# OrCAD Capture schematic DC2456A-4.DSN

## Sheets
1 PAGE3: size A
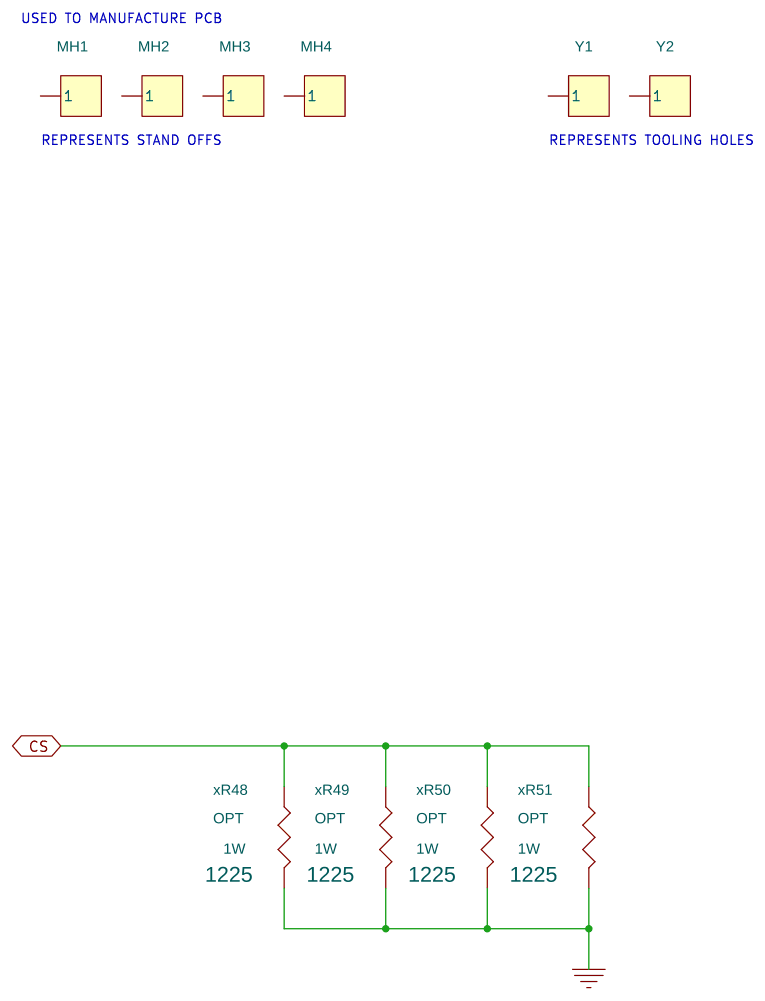
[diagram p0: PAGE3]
2 PAGE2: size B; title: HIGH EFFICIENCY HIGH VOLTAGE; rev: 4; company: TM; note: BUCK-BOOST CONVERTER
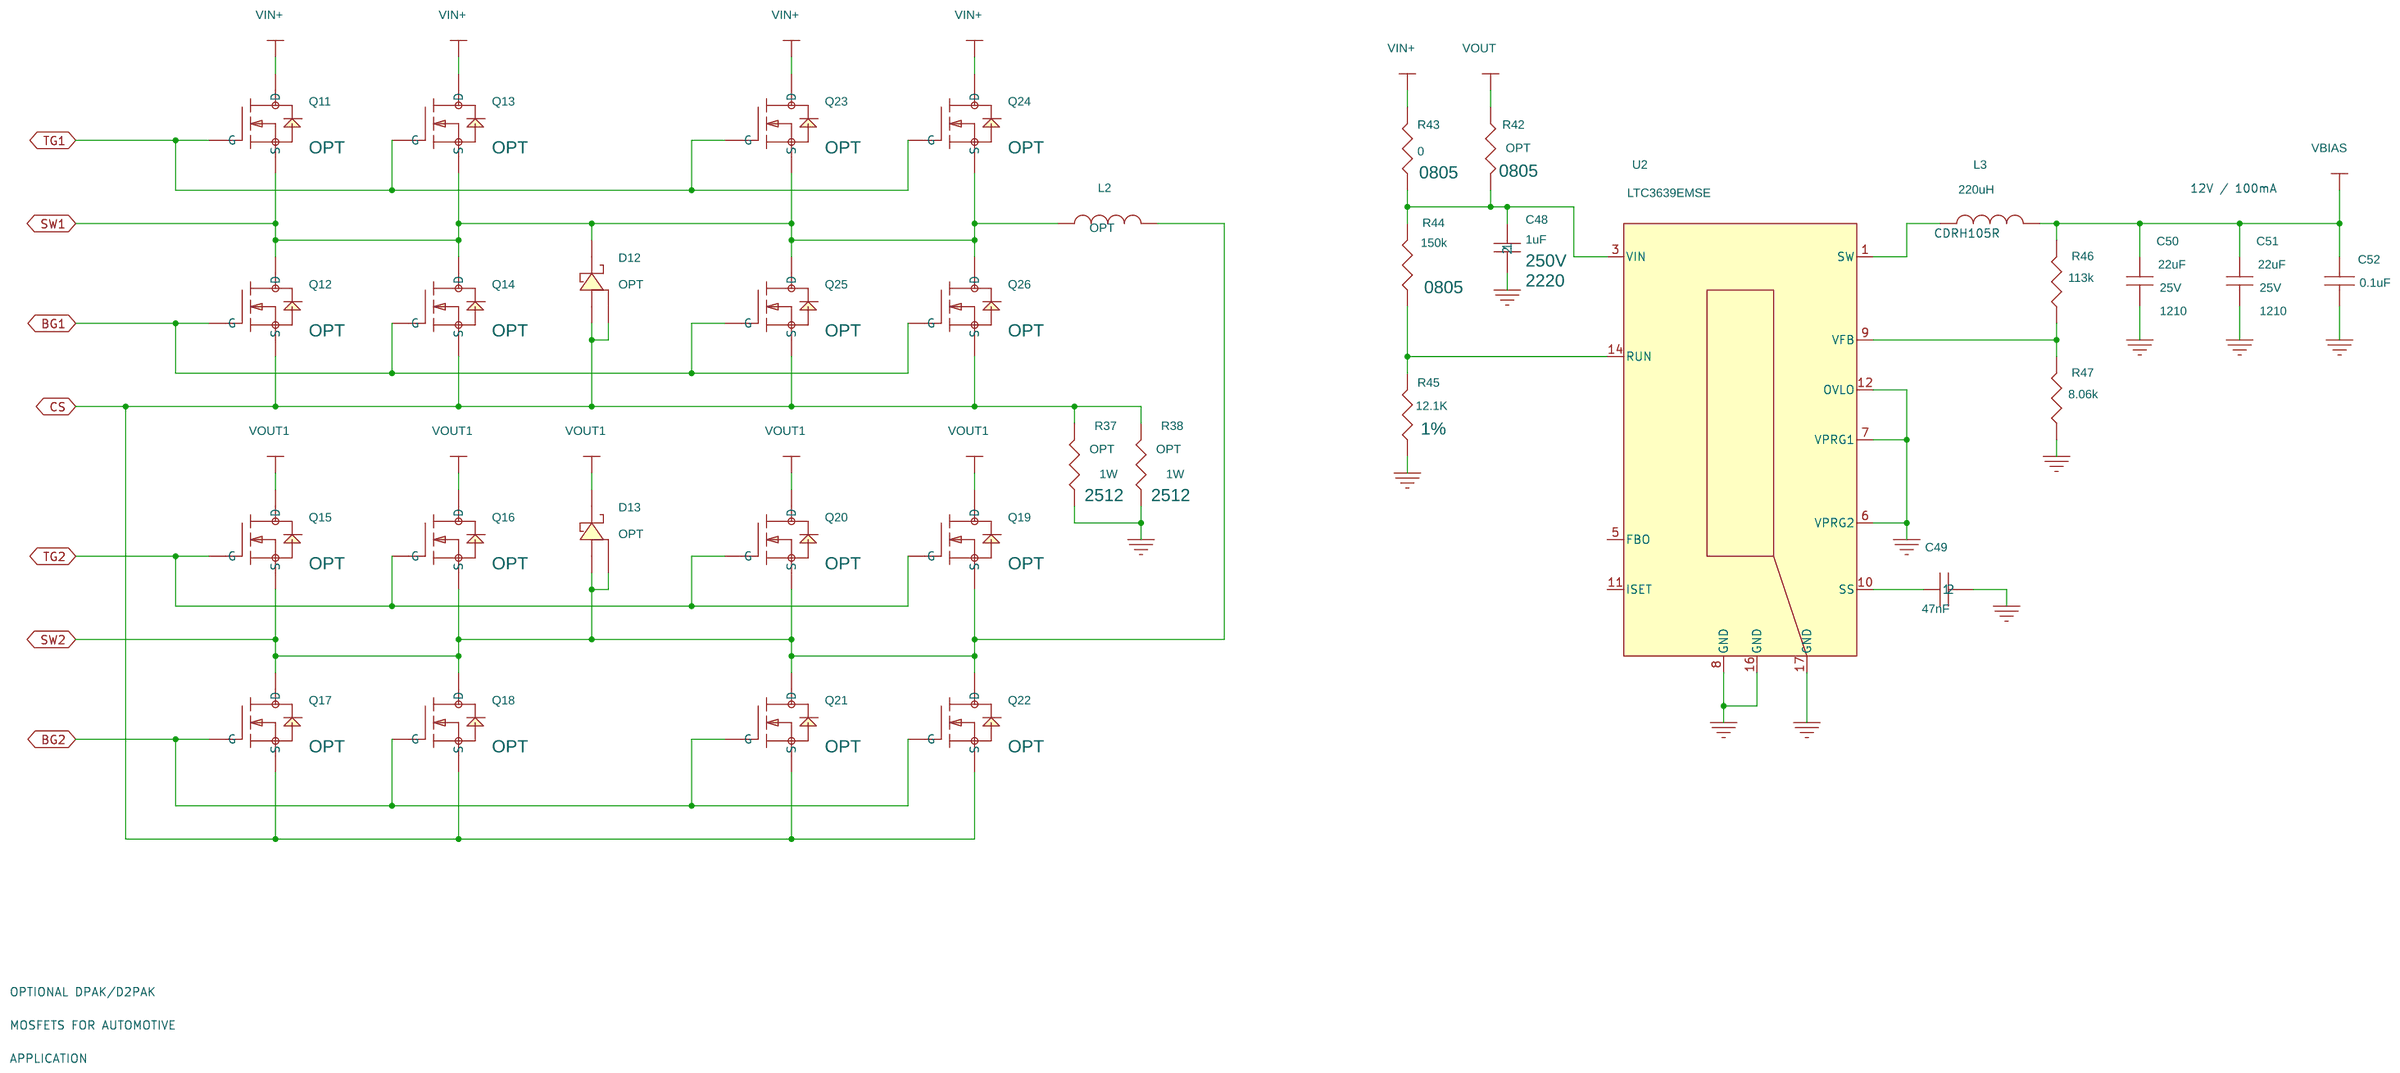
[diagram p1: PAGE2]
3 PAGE1: size Custom; title: HIGH EFFICIENCY HIGH VOLTAGE; rev: 4; company: TM; note: BUCK-BOOST CONVERTER
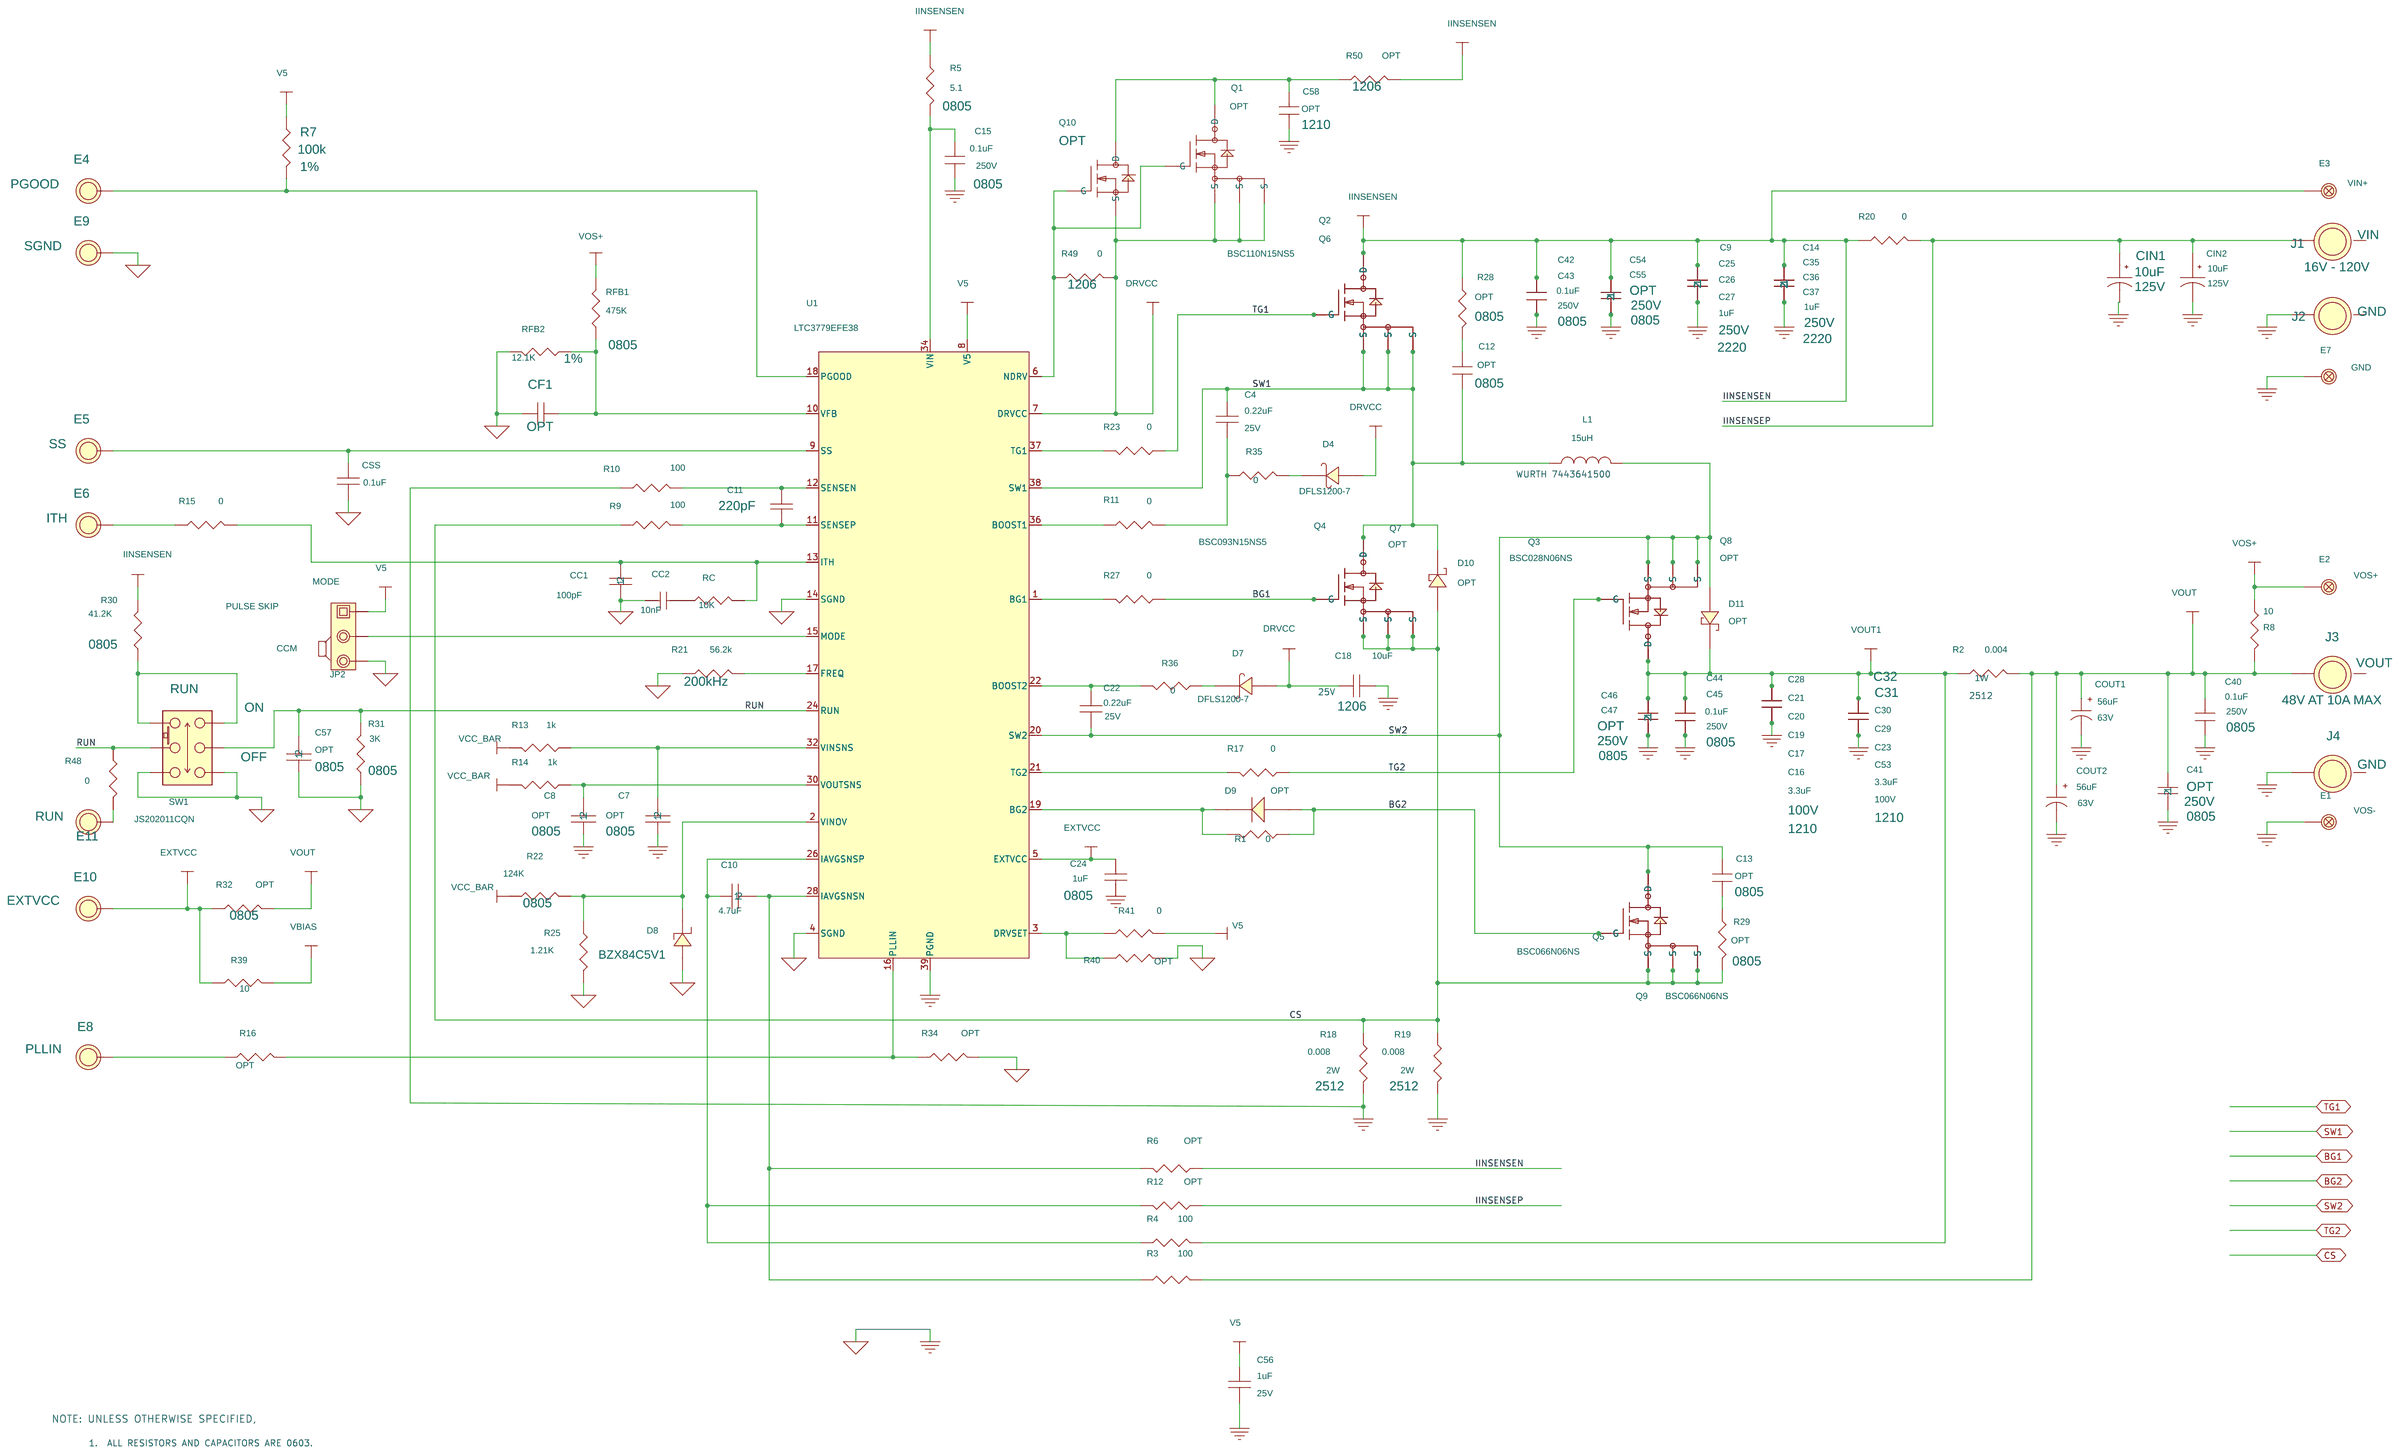
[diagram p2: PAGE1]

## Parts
sheet PAGE1
C4  0.22uF  [0603]
C7  OPT  [0805]
C8  OPT  [0805]
C9  1uF  [2220]
C10  4.7uF  [0603]
C11  220pF  [0603]
C12  OPT  [0805]
C13  OPT  [0805]
C14  1uF  [2220]
C15  0.1uF  [0805]
C16  3.3uF  [1210]
C17  3.3uF  [1210]
C18  10uF  [1206]
C19  3.3uF  [1210]
C20  3.3uF  [1210]
C21  3.3uF  [1210]
C22  0.22uF  [0603]
C23  3.3uF  [1210]
C24  1uF  [0805]
C25  1uF  [2220]
C26  1uF  [2220]
C27  1uF  [2220]
C28  3.3uF  [1210]
C29  3.3uF  [1210]
C30  3.3uF  [1210]
C31  3.3uF  [1210]
C32  3.3uF  [1210]
C35  1uF  [2220]
C36  1uF  [2220]
C37  1uF  [2220]
C40  0.1uF  [0805]
C41  0.1uF  [0805]
C42  0.1uF  [0805]
C43  0.1uF  [0805]
C44  0.1uF  [0805]
C45  0.1uF  [0805]
C46  0.1uF  [0805]
C47  0.1uF  [0805]
C53  3.3uF  [1210]
C54  0.1uF  [0805]
C55  0.1uF  [0805]
C56  1uF  [0603]
C57  OPT  [0805]
C58  OPT  [1210]
CC1  100pF  [0603]
CC2  10nF  [0603]
CF1  OPT  [0603]
CIN1  10uF  [CAP\SUN\10.3X10.3]
CIN2  10uF  [CAP\SUN\10.3X10.3]
COUT1  56uF  [CAP\SANYO\SVP\F8\10.3X10.3]
COUT2  56uF  [CAP\SANYO\SVP\F8\10.3X10.3]
CSS  0.1uF  [0603]
D4  DFLS1200-7  [POWERDI123]
D7  DFLS1200-7  [POWERDI123]
D8  BZX84C5V1  [SOT23]
D9  OPT  [SOT23]
D10  OPT  [SMB]
D11  OPT  [SMA-DIODE]
E1  Testpoint  [TP\MMX\2308-2]
E2  Testpoint  [TP\MMX\2308-2]
E3  Testpoint  [TP\MMX\2308-2]
E4  3A  [TP\MMX\2501-2]
E5  3A  [TP\MMX\2501-2]
E6  3A  [TP\MMX\2501-2]
E7  Testpoint  [TP\MMX\2308-2]
E8  3A  [TP\MMX\2501-2]
E9  3A  [TP\MMX\2501-2]
E10  3A  [TP\MMX\2501-2]
E11  3A  [TP\MMX\2501-2]
J1  VIN  [RP325/205]
J2  GND  [RP325/205]
J3  VOUT  [RP325/205]
J4  GND  [RP325/205]
JP2  3 Pins 2mm Ctrs.  [COMMCON2802S03G2]
L1  15uH  [IND\WRTH\7443641500]
Q1  OPT  [XSTR\INFINEON\PG-TDSON-8]
Q2  BSC093N15NS5  [XSTR\INFINEON\PG-TDSON-8]
Q3  BSC028N06NS  [XSTR\INFINEON\PG-TDSON-8]
Q4  BSC093N15NS5  [XSTR\INFINEON\PG-TDSON-8]
Q5  BSC066N06NS  [XSTR\INFINEON\PG-TDSON-8]
Q6  BSC110N15NS5  [XSTR\INFINEON\PG-TDSON-8]
Q7  OPT  [XSTR\INFINEON\PG-TDSON-8]
Q8  OPT  [XSTR\INFINEON\PG-TDSON-8]
Q9  BSC066N06NS  [XSTR\INFINEON\PG-TDSON-8]
Q10  OPT  [TO252AA]
R1  0  [0603]
R2  0.004  [RL3720T-R018-F]
R3  100  [0603]
R4  100  [0603]
R5  5.1  [0805]
R6  OPT  [0603]
R7  100k  [0603]
R8  10  [0603]
R9  100  [0603]
R10  100  [0603]
R11  0  [0603]
R12  OPT  [0603]
R13  1k  [0603]
R14  1k  [0603]
R15  0  [0603]
R16  OPT  [0603]
R17  0  [0603]
R18  0.008  [2512]
R19  0.008  [2512]
R20  0  [RN5326]
R21  56.2k  [0603]
R22  124K  [0805]
R23  0  [0603]
R25  1.21K  [0603]
R27  0  [0603]
R28  OPT  [0805]
R29  OPT  [0805]
R30  41.2K  [0805]
R31  3K  [0805]
R32  OPT  [0805]
R34  OPT  [0603]
R35  0  [0603]
R36  0  [0603]
R39  10  [0603]
R40  OPT  [0603]
R41  0  [0603]
R48  0  [0603]
R49  0  [1206]
R50  OPT  [1206]
RC  10K  [0603]
RFB1  475K  [0805]
RFB2  12.1K  [0603]
SW1  JS202011CQN  [JS202011]
U1  LTC3779EFE38  [LT_FE38_31_4.4]
XJP2  2mm Ctrs.
sheet PAGE2
C48  1uF  [2220]
C49  47nF  [0603]
C50  22uF  [1210]
C51  22uF  [1210]
C52  0.1uF  [0603]
D12  OPT  [POWERDI_5]
D13  OPT  [POWERDI_5]
L2  OPT  [IND\WRTH\7443641500]
L3  220uH  [IND\SUMIDA\CDRH105R\12X12]
Q11  SQD25N15-52-GE3  [TO252AA]
Q12  SQD25N15-52-GE3  [TO252AA]
Q13  SQM85N15-19-GE3  [TO263]
Q14  SQM85N15-19-GE3  [TO263]
Q15  SQD25N15-52-GE3  [TO252AA]
Q16  SQM85N15-19-GE3  [TO263]
Q17  SQD25N15-52-GE3  [TO252AA]
Q18  SQM85N15-19-GE3  [TO263]
Q19  SQM85N15-19-GE3  [TO263]
Q20  SQD25N15-52-GE3  [TO252AA]
Q21  SQD25N15-52-GE3  [TO252AA]
Q22  SQM85N15-19-GE3  [TO263]
Q23  SQD25N15-52-GE3  [TO252AA]
Q24  SQM85N15-19-GE3  [TO263]
Q25  SQD25N15-52-GE3  [TO252AA]
Q26  SQM85N15-19-GE3  [TO263]
R37  OPT  [2512]
R38  OPT  [2512]
R42  OPT  [0805]
R43  0  [0805]
R44  150k  [0805]
R45  12.1K  [0603]
R46  113k  [0603]
R47  8.06k  [0603]
U2  LTC3639EMSE  [LT_MSE16_12]
sheet PAGE3
MH1  CON1  [KEYSTONE_8831]
MH2  CON1  [KEYSTONE_8831]
MH3  CON1  [KEYSTONE_8831]
MH4  CON1  [KEYSTONE_8831]
xR48  OPT  [1225]
xR49  OPT  [1225]
xR50  OPT  [1225]
xR51  OPT  [1225]
Y1  CON1  [TOOL\ALGNHL\70]
Y2  CON1  [TOOL\ALGNHL\70]

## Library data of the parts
C4 C22 = EMK107BJ224MA: CAP, 0603 0.22uF 20% 16V X7R; 1st Part Field: 25V; 3rd Part Field: X7R; 4th Part Field: KEMET; 5th Part Field: C0603C224K4RAC; Part Number: AVX 0603YC224MAT2A; VOLTAGE: 16V
C7 = C_1: CAP, 0805 OPTION; Part Number: OPTION
C8 = C_3: CAP, 0805 OPTION; Part Number: OPTION
C9 = C3225X5R1C226M_10: CAP, 2220 1uF 10% 250V X7R; 1st Part Field: 50V; 3rd Part Field: X7R; 4th Part Field: TDK; Part Number: MURATA GRM55DR72E105KW01L; VOLTAGE: 250V
C10 = C: CAP, 0603 4.7uF 10% 10V X5R; Part Number: MURATA GRM188R61A475KE15D; VOLTAGE: 10V
C11 = CAP0603: CAP, 0603 220pF 5% 100V C0G; Part Number: MURATA GRM1885C2A221JA01D
C12 C13 = CAP1206: CAP, 0805 OPTION; Part Number: OPTION
C14 = C3225X5R1C226M_8: CAP, 2220 1uF 10% 250V X7R; 1st Part Field: 1000V; 3rd Part Field: OPT; 4th Part Field: TDK; Part Number: MURATA GRM55DR72E105KW01L; VOLTAGE: 250V
C15 C40 C42-C45 = CAP1210: CAP, 0805 0.1uF 10% 250V X7T; 1ST PART FIELD: 250V; Part Number: TDK CGA4J3X7T2E104K125AE
C16 = C3225X7R1H335M_5: CAP, 1210 3.3uF 10% 50V X7R; 1st Part Field: 16V; 3rd Part Field: X5R; 5th Part Field: C3225X5R1C226M; Part Number: AVX 12105C335K4T2A
C17 = C3225X7R1H335M_1: CAP, 1210 3.3uF 10% 50V X7R; 1st Part Field: 100V; 3rd Part Field: X5R; 5th Part Field: C3225X5R1C226M; Part Number: AVX 12105C335K4T2A
C18 = C1608X5R0J475MT: CAP, 1206 10uF 20% 6.3V X5R; 1st Part Field: 10V; 4th Part Field: KEMET; 5th Part Field: C1206C106K4PAC; Part Number: AVX 12066D106MAT2A
C19 = C3225X7R1H335M_4: CAP, 1210 3.3uF 10% 50V X7R; 1st Part Field: 16V; 3rd Part Field: X5R; 5th Part Field: C3225X5R1C226M; Part Number: AVX 12105C335K4T2A
C20 = C3225X7R1H335M_7: CAP, 1210 3.3uF 10% 50V X7R; 1st Part Field: 16V; 3rd Part Field: X5R; 5th Part Field: C3225X5R1C226M; Part Number: AVX 12105C335K4T2A
C21 = C3225X7R1H335M_10: CAP, 1210 3.3uF 10% 50V X7R; 1st Part Field: 16V; 3rd Part Field: X5R; 5th Part Field: C3225X5R1C226M; Part Number: AVX 12105C335K4T2A
C23 = C3225X7R1H335M_2: CAP, 1210 3.3uF 10% 50V X7R; 1st Part Field: 100V; 3rd Part Field: X5R; 5th Part Field: C3225X5R1C226M; Part Number: AVX 12105C335K4T2A
C24 = LMK107BJ105MA: CAP, 0805 1uF 10% 50V X7R; 1st Part Field: 16V; 3rd Part Field: X7R; 5th Part Field: EMK107BJ105MA; Part Number: AVX 08055C105KAT2A
C25 = C3225X7R1H335M_11: CAP, 2220 1uF 10% 250V X7R; 1st Part Field: 1000V; 3rd Part Field: X7R; 4th Part Field: TDK; Part Number: MURATA GRM55DR72E105KW01L; VOLTAGE: 200V
C26 = C3225X5R1C226M_7: CAP, 2220 1uF 10% 250V X7R; 1st Part Field: 50V; 3rd Part Field: X7R; 4th Part Field: TDK; Part Number: MURATA GRM55DR72E105KW01L; VOLTAGE: 200V
C27 = C3225X5R1C226M_6: CAP, 2220 1uF 10% 250V X7R; 1st Part Field: 50V; 3rd Part Field: X7R; 4th Part Field: TDK; Part Number: MURATA GRM55DR72E105KW01L; VOLTAGE: 200V
C28 = C3225X7R1H335M_9: CAP, 1210 3.3uF 10% 50V X7R; 1st Part Field: 16V; 3rd Part Field: X5R; 5th Part Field: C3225X5R1C226M; Part Number: AVX 12105C335K4T2A
C29 = C3225X7R1H335M: CAP, 1210 3.3uF 10% 50V X7R; 1st Part Field: 100V; 3rd Part Field: X5R; 5th Part Field: C3225X5R1C226M; Part Number: AVX 12105C335K4T2A
C30 = C3225X7R1H335M_12: CAP, 1210 3.3uF 10% 50V X7R; 1st Part Field: 100V; 3rd Part Field: X5R; 5th Part Field: C3225X5R1C226M; Part Number: AVX 12105C335K4T2A
C31 = C3225X7R1H335M_3: CAP, 1210 3.3uF 10% 50V X7R; 1st Part Field: 100V; 3rd Part Field: X5R; 5th Part Field: C3225X5R1C226M; Part Number: AVX 12105C335K4T2A
C32 = C3225X7R1H335M_6: CAP, 1210 3.3uF 10% 50V X7R; 1st Part Field: 100V; 3rd Part Field: X5R; 5th Part Field: C3225X5R1C226M; Part Number: AVX 12105C335K4T2A
C35 = C3225X5R1C226M_3: CAP, 2220 1uF 10% 250V X7R; 1st Part Field: 1000V; 3rd Part Field: OPT; 4th Part Field: TDK; Part Number: MURATA GRM55DR72E105KW01L; VOLTAGE: 250V
C36 = C3225X5R1C226M: CAP, 2220 1uF 10% 250V X7R; 1st Part Field: 1000V; 3rd Part Field: OPT; 4th Part Field: TDK; Part Number: MURATA GRM55DR72E105KW01L; VOLTAGE: 250V
C37 = C3225X5R1C226M_5: CAP, 2220 1uF 10% 250V X7R; 1st Part Field: 1000V; 3rd Part Field: OPT; 4th Part Field: TDK; Part Number: MURATA GRM55DR72E105KW01L; VOLTAGE: 250V
C41 = C3225X5R1C226M_11: CAP, 0805 0.1uF 10% 250V X7T OPTION; 1st Part Field: 1000V; 3rd Part Field: OPT; 4th Part Field: TDK; Part Number: TDK CGA4J3X7T2E104K125AE OPTION; VOLTAGE: 250V
C46 = C3225X5R1C226M_4: CAP, 0805 0.1uF 10% 250V X7T OPTION; 1st Part Field: 1000V; 3rd Part Field: OPT; 4th Part Field: TDK; Part Number: TDK CGA4J3X7T2E104K125AE OPTION; VOLTAGE: 250V
C47 = C3225X5R1C226M_2: CAP, 0805 0.1uF 10% 250V X7T OPTION; 1st Part Field: 1000V; 3rd Part Field: OPT; 4th Part Field: TDK; Part Number: TDK CGA4J3X7T2E104K125AE OPTION
C53 = C3225X7R1H335M_8: CAP, 1210 3.3uF 10% 50V X7R; 1st Part Field: 100V; 3rd Part Field: X5R; 5th Part Field: C3225X5R1C226M; Part Number: AVX 12105C335K4T2A
C54 = C3225X5R1C226M_9: CAP, 0805 0.1uF 10% 250V X7T OPTION; 1st Part Field: 1000V; 3rd Part Field: OPT; 4th Part Field: TDK; Part Number: TDK CGA4J3X7T2E104K125AE OPTION; VOLTAGE: 250V
C55 = C3225X5R1C226M_1: CAP, 0805 0.1uF 10% 250V X7T OPTION; 1st Part Field: 1000V; 3rd Part Field: OPT; 4th Part Field: TDK; Part Number: TDK CGA4J3X7T2E104K125AE OPTION
C56 = EMK107BJ224MA: CAP, 0603 1uF 10% 50V X5R; 1st Part Field: 25V; 3rd Part Field: X7R; 4th Part Field: KEMET; 5th Part Field: C0603C224K4RAC; Part Number: TDK C1608X5R1H105K080AB; VOLTAGE: 50V
C57 = C_2: CAP, 0805 OPTION; Part Number: OPTION
C58 = CAP1206: CAP, 1210 OPTION; Part Number: OPTION
CC1 = 06035A470KAT1A: CAP, 0603 100pF 10% 50V C0G; 5th Part Field: 06035A470KAT2A; Part Number: AVX 06035A101KAT2A
CC2 = 06033C103KAT2A: CAP, 0603 10nF 10% 50V X7R; Part Number: AVX 06035C103KAT2A
CF1 = CAP_NP: CAP, 0603 OPTION; Case: 0805; Part Number: OPTION; Tolerance: X5R; Voltage: 6.3V
CIN1 = 35SVPD22M: CAP, 10uF 20% 125V ELEC; 1st Part Field: 125V; 5th Part Field: 50ME270WX; Part Number: SUNCON 125HVH10M
CIN2 = 35SVPD22M_1: CAP, 10uF 20% 125V ELEC; 1st Part Field: 125V; 5th Part Field: 50ME270WX; Part Number: SUNCON 125HVH10M
COUT1 COUT2 = CAP-OS-CON-F13: CAP, 56uF 20% 63V HYB POLYMER; 1ST PART FIELD: 63V; Part Number: UNITED CHEMI-CON HHXA630ARA560MJA0
C52 CSS = 06033C223KAT1A: CAP, 0603 0.1uF 10% 50V X7R; 5th Part Field: 06033C223KAT2A; Part Number: AVX 06035C104KAT2A
D4 D7 = DFLS160_0: DIODE, SCHOTTKY 1A 200V POWERDI123; Part Number: DIODES INC. DFLS1200-7
D8 = BZX84C2V4-C51: DIODE, ZENER 5.1V 350mW SOT23-3; Part Number: DIODES INV. BZX84C5V1-7-F
D9 = BAS16_SOT_0: DIODE, OPTION; Part Number: DIODES INC. BAS16-7-F OPTION
D10 = DIODE_SCHOTTKY_1: DIODE, SCHOTTKY OPTION SMB; Part Number: OPTION
D11 = DIODE_SCHOTTKY_1: DIODE, SCHOTTKY OPTION SMA; Part Number: OPTION
E1 = mill-max-2308-2: TURRET; 9th Part Field: VOS-; Part Number: MILL-MAX 2308-2-00-80-00-00-07-0
E2 = mill-max-2308-2: TURRET; 9th Part Field: VOS+; Part Number: MILL-MAX 2308-2-00-80-00-00-07-0
E3 = mill-max-2308-2: TURRET; 9th Part Field: VIN+; Part Number: MILL-MAX 2308-2-00-80-00-00-07-0
E4 = E_4: TURRET; INPUT: PGOOD; Part Number: MILL-MAX 2501-2-00-80-00-00-07-0; STATUS: 1.6V, 1.8V, 2.0V OR 2.5V @ 15A
E5 = E_4: TURRET; INPUT: SS; Part Number: MILL-MAX 2501-2-00-80-00-00-07-0; STATUS: 1.6V, 1.8V, 2.0V OR 2.5V @ 15A
E6 = E_4: TURRET; INPUT: ITH; Part Number: MILL-MAX 2501-2-00-80-00-00-07-0; STATUS: 1.6V, 1.8V, 2.0V OR 2.5V @ 15A
E7 = mill-max-2308-2: TURRET; 9th Part Field: GND; Part Number: MILL-MAX 2308-2-00-80-00-00-07-0
E8 = E_4: TURRET; INPUT: PLLIN; Part Number: MILL-MAX 2501-2-00-80-00-00-07-0; STATUS: 1.6V, 1.8V, 2.0V OR 2.5V @ 15A
E9 = E_4: TURRET; INPUT: SGND; Part Number: MILL-MAX 2501-2-00-80-00-00-07-0; STATUS: 1.6V, 1.8V, 2.0V OR 2.5V @ 15A
E10 = E_4: TURRET; INPUT: EXTVCC; Part Number: MILL-MAX 2501-2-00-80-00-00-07-0; STATUS: 1.6V, 1.8V, 2.0V OR 2.5V @ 15A
E11 = E_4: TURRET; INPUT: RUN; Part Number: MILL-MAX 2501-2-00-80-00-00-07-0; STATUS: 1.6V, 1.8V, 2.0V OR 2.5V @ 15A
J1 = E_18: JACK, BANANA; 1st Part Field: 16V - 120V; Part Number: KEYSTONE 575-4
J2 J4 = E_18: JACK, BANANA; Part Number: KEYSTONE 575-4
J3 = E_18: JACK, BANANA; 1st Part Field: 48V AT 10A MAX; Part Number: KEYSTONE 575-4
JP2 = Samtec_TMM-103-02-L-S: HEADER, 3PIN 2mm; 11th Part Field: CCM; 12th Part Field: MODE; 9th Part Field: PULSE SKIP; Part Number: SAMTEC TMM-103-02-L-S
L1 = FDA1254-4R7M_2: IND, 15uH; Part Number: WURTH 7443641500
Q1 = MOSFET_N-CHANNEL_SO8_3: XSTR, OPTION; 1st Part Field: INFINEON BSC190N15NS3G; Part Number: OPTION
Q2 Q6 = MOSFET_N-CHANNEL_SO8_1: XSTR, N-CHANNEL POWER MOSFET; Part Number: INFINEON BSC110N15NS5
Q3 = MOSFET_N-CHANNEL_SO8_1: XSTR, N-CHANNEL POWER MOSFET; Part Number: INFINEON BSC028N06NS
Q4 = MOSFET_N-CHANNEL_SO8_1: XSTR, N-CHANNEL POWER MOSFET; Part Number: INFINEON BSC093N15NS5
Q5 Q9 = MOSFET_N-CHANNEL_SO8_1: XSTR, N-CHANNEL POWER MOSFET; Part Number: INFINEON BSC066N06NS
Q7 Q8 = MOSFET_N-CHANNEL_SO8_1: XSTR, OPTION; Part Number: OPTION
Q10 = MOSFET_N-CHANNEL: XSTR, OPTION TO-252; Part Number: OPTION
R1 R11 R35 R36 = R: RES, 0 OHM JUMPER; Part Number: VISHAY CRCW06030000Z0EA
R2 = RL3720WT-R018-G: RES, 2512 0.004 OHMS 1% 1W; 2nd Part Field: 1W; 5th Part Field: RL3720WT-R004-G; Part Number: PANASONIC ERJ-M1WSF4M0U
R3 R4 = R: RES, 0603 100 OHMS 1% 0.1W; Part Number: VISHAY CRCW0603100RFKEA
R5 = CR10-100JM: RE, 0805 5.1 OHMS 5% 0.125W; Part Number: VISHAY CRCW08055R10JNEA
R6 R12 = R: RES, 0603 OPTION; Part Number: OPTION
R7 = RESISTOR: RES, 0603 100K OHM 1% 0.1W; Part Number: VISHAY CRCW0603100KFKEA; Tol: 1%
R8 = CR16-100JM: RES, 0603 10 OHMS 5% 0.1W; Part Number: VISHAY CRCW060310R0JNEA
R9 R10 = CR16-1241FM: RES, 0603 100 OHMS 1% 0.1W; Part Number: VISHAY CRCW0603100RFKEA
R13 R14 = R: RES, 0603 1k OHMS 1% 0.1W; Part Number: VISHAY CRCW06031K00FKEA
R15 R48 = CR16-1241FM: RES, 0 OHM JUMPER; Part Number: VISHAY CRCW06030000Z0EA
R16 R34 = CR16-1241FM: RES, 0603 OPTION; Part Number: OPTION
R17 R23 R27 = CR10-100JM: RES, 0 OHM JUMPER; Part Number: VISHAY CRCW06030000Z0EA
R18 R19 = RL3720WT-R018-G: RES, 2512 0.008 OHMS 1% 2W; 2nd Part Field: 2W; 5th Part Field: RL3720WT-R010-G; Part Number: BOURNS CRE2512-FZ-R008E-2
R20 = RL3720WT-R018-G: RES, 2512 0 OHM JUMPER; 5th Part Field: RL3720WT-R010-G; Part Number: TEPRO RN5326
R21 = CR16-1002FM_3: RES, 0603 56.2k OHMS 1% 0.1W; 1st Part Field: 200kHz; Part Number: VISHAY CRCW060356K2FKEA
R22 = CR16-1002FM_4: RES, 0805 124K OHMS 1% 0.125W; Part Number: VISHAY CRCW0805124KFKEA
R25 = CR16-1002FM_1: RES, 0603 1.21K OHMS 1% 0.1W; Part Number: VISHAY CRCW06031K21FKEA
R28 R29 = AAC-1206: RES, 0805 OPTION; Part Number: OPTION
R30 = CR16-8061FM: RES, 0805 41.2K OHMS 1% 0.125W; Part Number: VISHAY CRCW080541K2FKEA
R31 = CR16-8061FM: RES, 0805 3K OHMS 1% 0.125W; Part Number: VISHAY CRCW08053K00FKEA
R32 = CR16-1241FM: RES, 0805 OPTION; Part Number: OPTION
R39 = CR16-1241FM: RES, 0603 10 OHMS 5% 0.1W; Part Number: VISHAY CRCW060310R0JNEA
R40 = CR16-1002FM_2: RES, 0603 OPTION; Part Number: OPTION
R41 = CR16-1002FM: RES, 0 OHM JUMPER; Part Number: VISHAY CRCW06030000Z0EA
R49 = R: RES, 1206 0 OHM JUMPER; Part Number: VISHAY CRCW12060000Z0EA
R50 = R: RES, 1206 OPT; Part Number: OPTION
RC = CR16-1003FM: RES, 0603 10K OHMS 5% 0.1W; Part Number: VISHAY CRCW060310K0JNEA
RFB1 = CR16-1133FM: RES, 0805 475K OHMS 1% 0.125W; Part Number: VISHAY CRCW0805475KFKEA
R45 RFB2 = CR16-8061FM: RES, 0603 12.1K OHMS 1% 0.1W; Part Number: VISHAY CRCW060312K1FKEA; Tolerance: 1%
SW1 = SW_3: SWITCH, SUB=MINIATURE SLIDE 300mA 6V; 1st Part Field: RUN; 2nd Part Field: ON; 3rd Part Field: OFF; Part Number: C&K JS202011CQN
U1 = LTC3779EFE_1: IC, BUCK-BOOST CONVERTER; Part Number: LINEAR TECH. LTC3779EFE38
XJP2 = Samtec_2SN-BK-G: SHUNT 2mm; Part Number: SAMTEC 2SN-BK-G
C48 = C3225X5R1C226M: CAP, 2220 1uF 10% 250V X7R; 1st Part Field: 50V; 3rd Part Field: X7R; 4th Part Field: TDK; Part Number: MURATA GRM55DR72E105KW01L; VOLTAGE: 250V
C49 = C: CAP, 0603 47nF 10% 50V X7R; Part Number: MURATA GRM188R71H473KA61D
C50 = C3225X5R0J476M: CAP, 1210 22uF 20% 16V X5R; 1st Part Field: 25V; 4th Part Field: Taiyo Yuden; 5th Part Field: TDK C3225X5R1C226MT; Part Number: AVX 1210YD226MAT2A
C51 = C3225X5R0J476M_1: CAP, 1210 22uF 20% 16V X5R; 1st Part Field: 25V; 4th Part Field: Taiyo Yuden; 5th Part Field: TDK C3225X5R1C226MT; Part Number: AVX 1210YD226MAT2A
D12 D13 = DIODE_SCHOTTKY_0: DIODE, SCHOTTKY OPTION POWERDI5; Part Number: OPTION
L2 = FDA1254-4R7M_2: IND, OPTION; 1st Part Field: SER2918H-223KL; Part Number: OPTION
L3 = FDA1254-4R7M: IND, 220uH; Part Number: SUMIDA CDRH105RNP-221NC
Q11 Q12 Q15 Q17 Q20 Q21 Q23 Q25 = MOSFET_N-CHANNEL: XSTR, AUTOMOTIVE MOSFET OPTION; 1st Part Field: OPT; Part Number: OPTION
Q13 Q16 Q19 Q24 = MOSFET_N-CHANNEL_2: XSTR, AUTOMOTIVE MOSFET OPTION; 1st Part Field: OPT; Part Number: OPTION
Q14 Q18 Q22 Q26 = MOSFET_N-CHANNEL_3: XSTR, AUTOMOTIVE MOSFET OPTION; 1st Part Field: OPT; Part Number: OPTION
R37 R38 = RL3720WT-R018-G: RES, 2512 0.01 OHMS 1% 1W OPTION; 2nd Part Field: 1W; 5th Part Field: RL3720WT-R010-G; Part Number: VISHAY WSL2512R0100FEA OPTION
R42 = R: RES, 0805 OPTION; Part Number: OPTION
R43 = CR16-1241FM: RES, 0805 0 OHM JUMPER; Part Number: VISHAY CRCW08050000Z0EA
R44 = CR16-1002FM_2: RES, 0805 150K OHMS 1% 0.125W; Part Number: VISHAY CRCW0805150KFKEA
R46 = CR16-1002FM_1: RES, 0603 113K OHMS 1% 0.1W; Part Number: VISHAY CRCW0603113KFKEA
R47 = CR16-1002FM: RES, 0603 8.06K OHMS 1% 0.1W; Part Number: VISHAY CRCW06038K06FKEA
U2 = LTC3630EMSE_1: IC, SYNCHRONOUS STEP-DOWN REGULATOR; Part Number: LINEAR TECH. LTC3639EMSE
MH1-MH4 = CON1: STANDOFF, SNAP ON 9.525mm; Part Number: KEYSTONE 8834
xR48-xR51 = RL3720WT-R018-G: RES, 1225 OPTION; 2nd Part Field: 1W; 5th Part Field: RL3720WT-R010-G; Part Number: OPTION
Y1 Y2 = CON1: DO NOT STUFF; Part Number: PADS ONLY

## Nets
GND: C7.1 C8.1 C9.2 C14.2 C15.2 C16.2 C17.2 C18.2 C19.2 C20.2 C21.2 C23.2 C24.2 C25.2 C26.2 C27.2 C28.2 C29.2 C30.2 C31.2 C32.2 C35.2 C36.2 C37.2 C40.2 C41.2 C42.2 C43.2 C44.2 C45.2 C46.2 C47.2 C48.2 C49.2 C50.2 C51.2 C52.2 C53.2 C54.2 C55.2 C56.2 C58.2 CIN1.2 CIN2.2 COUT1.2 COUT2.2 E1.1 E7.1 J2.1(A) J4.1(A) R10.1 R18.2 R19.2 R37.2 R38.2 R45.1 R47.1 U1.39(PGND) U2.6(VPRG2) U2.7(VPRG1) U2.8(GND) U2.12(OVLO) U2.16(GND) U2.17(GND) xR48.2 xR49.2 xR50.2 xR51.2
GND_SIGNAL: C57.1 CC1.1 CC2.1 CF1.2 CSS.2 D8.1(ANODE) E9.1(A) JP2.3 R21.1 R25.1 R31.2 R34.2 R40.2 RFB2.2 SW1.3 SW1.6 U1.4(SGND) U1.14(SGND)
V5: C56.1 JP2.1 R7.1 R41.2 U1.8(V5)
VIN+: C9.1 C14.1 C25.1 C26.1 C27.1 C35.1 C36.1 C37.1 C42.1 C43.1 C54.1 C55.1 E3.1 Q2.5(D) Q6.5(D) Q11.3(D) Q13.2(D) Q23.3(D) Q24.2(D) R5.1 R6.1 R13.1 R20.1 R22.2 R28.1 R30.2 R43.2 R50.2
BG1: Q4.4(G) Q7.4(G) Q12.1(G) Q14.1(G) Q25.1(G) Q26.1(G) R27.1
BG2: D9.1(ANODE) Q5.4(G) Q9.4(G) Q17.1(G) Q18.1(G) Q21.1(G) Q22.1(G) R1.2
CS: D10.2(ANODE) D12.1(ANODE) D12.2(ANODE) Q4.1(S) Q4.2(S) Q4.3(S) Q5.1(S) Q5.2(S) Q5.3(S) Q7.1(S) Q7.2(S) Q7.3(S) Q9.1(S) Q9.2(S) Q9.3(S) Q12.2(S) Q14.3(S) Q17.2(S) Q18.3(S) Q21.2(S) Q22.3(S) Q25.2(S) Q26.3(S) R9.1 R18.1 R19.1 R29.2 R37.1 R38.1 xR48.1 xR49.1 xR50.1 xR51.1
DRVCC: C18.1 D4.2(ANODE) D7.2(ANODE) Q1.1(S) Q1.2(S) Q1.3(S) Q10.2(S) R49.2 U1.7(DRVCC)
EXTVCC: C24.1 E10.1(A) R32.1 R39.1 U1.5(EXTVCC)
IINSENSEP: CIN1.1 CIN2.1 J1.1(A) R12.1 R20.2
RUN: C57.2 R31.1 R48.2 SW1.2 SW1.5 U1.24(RUN)
SW1: C4.1 C12.2 D10.1(CATHODE) D12.3(CATHODE) L1.2 L2.1 Q2.1(S) Q2.2(S) Q2.3(S) Q4.5(D) Q6.1(S) Q6.2(S) Q6.3(S) Q7.5(D) Q11.2(S) Q12.3(D) Q13.3(S) Q14.2(D) Q23.2(S) Q24.3(S) Q25.3(D) Q26.2(D) U1.38(SW1)
SW2: C13.1 C22.2 D11.2(ANODE) D13.1(ANODE) D13.2(ANODE) L1.1 L2.2 Q3.1(S) Q3.2(S) Q3.3(S) Q5.5(D) Q8.1(S) Q8.2(S) Q8.3(S) Q9.5(D) Q15.2(S) Q16.3(S) Q17.3(D) Q18.2(D) Q19.3(S) Q20.2(S) Q21.3(D) Q22.2(D) U1.20(SW2)
TG1: Q2.4(G) Q6.4(G) Q11.1(G) Q13.1(G) Q23.1(G) Q24.1(G) R23.1
TG2: Q3.4(G) Q8.4(G) Q15.1(G) Q16.1(G) Q19.1(G) Q20.1(G) R17.1
VBIAS: C50.1 C51.1 C52.1 L3.2 R39.2 R46.2
VOS+: E2.1 R8.2 RFB1.1
VOUT: C40.1 C41.1 COUT1.1 COUT2.1 J3.1(A) R2.2 R3.2 R8.1 R14.1 R32.2 R42.1
VOUT1: C16.1 C17.1 C19.1 C20.1 C21.1 C23.1 C28.1 C29.1 C30.1 C31.1 C32.1 C44.1 C45.1 C46.1 C47.1 C53.1 D11.1(CATHODE) D13.3(CATHODE) Q3.5(D) Q8.5(D) Q15.3(D) Q16.2(D) Q19.2(D) Q20.3(D) R2.1 R4.2
N965368: E4.1(A) R7.2 U1.18(PGOOD)
N967628: CSS.1 E5.1(A) U1.9(SS)
N1026360: C11.1 R9.2 U1.11(SENSEP)
N1026362: C11.2 R10.2 U1.12(SENSEN)
N1091954: R23.2 U1.37(TG1)
N1110472: CF1.1 RFB1.2 RFB2.1 U1.10(VFB)
N16498430: C7.2 R13.2 U1.32(VINSNS)
N16499798: C8.2 R14.2 U1.30(VOUTSNS)
N16512527: C12.1 R28.2
N16546456: C10.2 R3.1 R6.2 U1.28(IAVGSNSN)
N16546474: C10.1 R4.1 R12.2 U1.26(IAVGSNSP)
N16563770: R21.2 U1.17(FREQ)
N16563853: JP2.2 U1.15(MODE)
N16565942: R11.1 U1.36(BOOST1)
N16566021: C4.2 R11.2 R35.1
N16566360: D9.3(CATHODE) R1.1 U1.19(BG2)
N16567067: C22.1 R36.1 U1.22(BOOST2)
N17426735: E6.1(A) R15.1
N17446218: R27.2 U1.1(BG1)
N17603641: E8.1(A) R16.1
N17642393: CC1.2 R15.2 RC.2 U1.13(ITH)
N17647085: D8.3(CATHODE) R22.1 R25.2 U1.2(VINOV)
N17654095: C13.2 R29.1
N17655419: C15.1 R5.2 U1.34(VIN)
N17719602: R17.2 U1.21(TG2)
N17719959: R16.2 R34.1 U1.16(PLLIN)
N17726582: C58.1 Q1.5(D) Q10.3(D) R50.1
N17739357: R40.1 R41.1 U1.3(DRVSET)
N17742117: Q1.4(G) Q10.1(G) R49.1 U1.6(NDRV)
N17747159: R44.1 R45.2 U2.14(RUN)
N17747344: C48.1 R42.2 R43.1 R44.2 U2.3(VIN)
N17748142: L3.1 U2.1(SW)
N17748272: R46.1 R47.2 U2.9(VFB)
N17748413: C49.1 U2.10(SS)
N17785276: D7.1(CATHODE) R36.2
N17796955: D4.1(CATHODE) R35.2
N17843593: R30.1 SW1.1 SW1.4
N17848731: E11.1(A) R48.1
N17863986: CC2.2 RC.1

Not connected (* = marked no-connect by the designer): MH1 1; MH2 1; MH3 1; MH4 1; U2 5(FBO) 11(ISET); Y1 1; Y2 1

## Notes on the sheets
sheet 1
- USED TO MANUFACTURE PCB
- REPRESENTS STAND OFFS
- REPRESENTS TOOLING HOLES
sheet 2
- 12V / 100mA
- CDRH105R
- OPTIONAL DPAK/D2PAK
- MOSFETS FOR AUTOMOTIVE
- APPLICATION
sheet 3
- WURTH 7443641500
- 25V
- 2512
- NOTE: UNLESS OTHERWISE SPECIFIED,
- 1.  ALL RESISTORS AND CAPACITORS ARE 0603.
